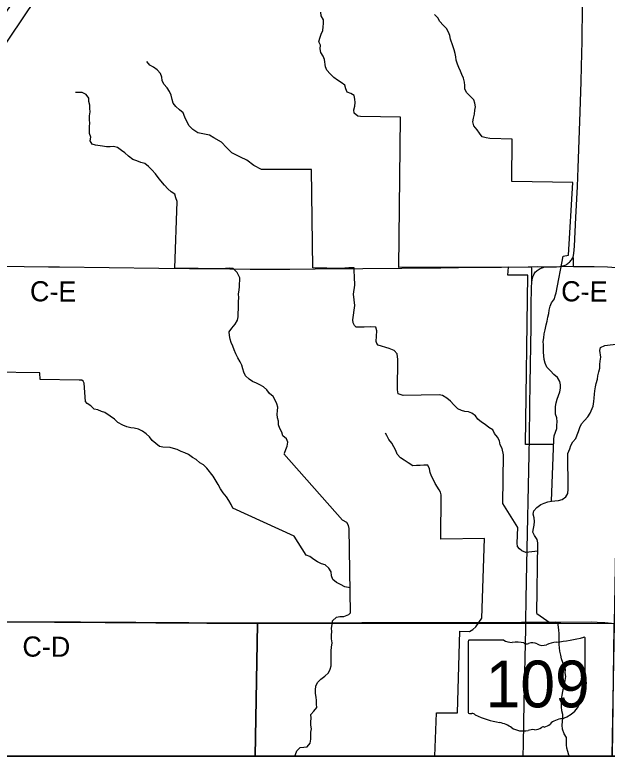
# Model space of a CAD drawing. Extents: x -21.7 to 34, y 0 to 22.
# Drawn here: x 25.914 to 27.584, y 14.078 to 16.19 of the extents above; entities that cross this region are included whole.
import ezdxf

# ---------------------------------------------------------------- set-up
doc = ezdxf.new("R2010")
doc.units = 0
for name, color, linetype in [('Default', 7, 'Continuous'), ('GM_X_County_Road', 7, 'Continuous'), ('GM_X_County_Road_Text', 7, 'Continuous'), ('GM_X_Interchange_Ramps', 7, 'Continuous'), ('GM_X_Minor_River', 7, 'Continuous'), ('GM_X_State_Location', 7, 'Continuous'), ('GM_X_State_Route', 7, 'Continuous'), ('GM_X_State_Shield', 7, 'Continuous'), ('GM_X_Township_Road', 7, 'Continuous'), ('SH_Data', 7, 'Continuous'), ('SH_Text', 7, 'Continuous')]:
    doc.layers.add(name, color=color, linetype=linetype)

msp = doc.modelspace()

# ---------------------------------------------------------------- linework, layer by layer
at = {"layer": 'Default'}
for points in [[(25.588, 14.1), (26.5915, 14.1), (26.5986, 14.4731), (25.5956, 14.4795)], [(26.5915, 14.1), (27.5993, 14.1), (27.6043, 14.466), (27.6038, 14.4739), (26.5986, 14.4731)]]:
    msp.add_lwpolyline(points, close=True, dxfattribs=at)
at = {"layer": 'GM_X_County_Road'}
for points in [[(27.4894, 15.481), (27.4896, 15.4845), (27.4893, 15.4993), (27.4893, 15.5015), (27.4892, 15.5035), (27.4892, 15.5045), (27.4888, 15.5064), (27.4882, 15.5073)], [(25.6145, 15.484), (25.6886, 15.4831), (25.7322, 15.4829), (25.785, 15.4821), (25.9404, 15.4804), (26.0088, 15.48), (26.0399, 15.4796), (26.3197, 15.4763), (26.4068, 15.4754), (26.4628, 15.4746), (26.5778, 15.4735), (26.6897, 15.4735), (26.7613, 15.474), (26.895, 15.4751), (27.1157, 15.4769), (27.1655, 15.4774), (27.2867, 15.4786), (27.3614, 15.4796), (27.3714, 15.4798)], [(27.4416, 15.48), (27.4508, 15.4806), (27.4543, 15.4811)], [(27.4543, 15.4811), (27.4623, 15.4811), (27.4894, 15.481)], [(27.4894, 15.481), (27.5228, 15.4808), (27.5477, 15.4805), (27.5851, 15.4792), (27.6231, 15.4773)], [(27.3714, 15.4798), (27.3893, 15.4802), (27.3987, 15.4799), (27.4084, 15.4794)], [(27.3717, 15.439), (27.3718, 15.4424), (27.372, 15.4475), (27.372, 15.4518), (27.3715, 15.4758), (27.3714, 15.4798)], [(27.4084, 15.4794), (27.4135, 15.4794), (27.4197, 15.4798), (27.4416, 15.48)], [(25.5958, 14.4815), (25.6644, 14.4811), (25.6954, 14.4811), (25.7576, 14.4806), (25.8197, 14.4801), (25.8788, 14.4799), (25.9627, 14.4791), (26.0311, 14.479), (26.0995, 14.4784), (26.1679, 14.4781), (26.255, 14.4775), (26.4042, 14.4765), (26.513, 14.476), (26.6187, 14.4755), (26.6965, 14.4758), (26.8923, 14.4765), (27.0291, 14.4769), (27.0913, 14.4771), (27.2374, 14.477), (27.3431, 14.4775), (27.3462, 14.4775), (27.355, 14.4777)], [(27.355, 14.4777), (27.4534, 14.4782), (27.5404, 14.4786), (27.556, 14.4782), (27.5778, 14.4767), (27.5963, 14.4748), (27.6052, 14.4738)]]:
    msp.add_lwpolyline(points, dxfattribs=at)
at = {"layer": 'GM_X_Interchange_Ramps'}
msp.add_lwpolyline([(23.5167, 14.1), (27.5987, 14.1), (27.605, 14.4744), (27.6229, 15.4779), (27.6372, 16.2146)], dxfattribs=at)
at = {"layer": 'GM_X_Minor_River'}
for points in [[(26.8888, 15.9039), (26.8816, 15.9048), (26.8712, 15.913), (26.8699, 15.9225), (26.8724, 15.9323), (26.8734, 15.9429), (26.8729, 15.9528), (26.8712, 15.9627), (26.8615, 15.9683), (26.8513, 15.9719), (26.8477, 15.9815), (26.8442, 15.9918), (26.8345, 15.9992), (26.824, 16.0059), (26.8136, 16.0137), (26.8032, 16.0235), (26.7936, 16.0339), (26.7896, 16.0435), (26.7871, 16.064), (26.7831, 16.0736), (26.7769, 16.0844), (26.7749, 16.0943), (26.7762, 16.1045), (26.7715, 16.1141), (26.7737, 16.1247), (26.7777, 16.1352), (26.7821, 16.1458), (26.7839, 16.1564), (26.7845, 16.1662), (26.784, 16.1757), (26.7778, 16.1869), (26.7773, 16.1975)], [(27.2535, 15.8418), (27.2436, 15.8432), (27.2323, 15.8465), (27.2246, 15.8561), (27.2176, 15.8658), (27.2084, 15.8774), (27.2056, 15.8881), (27.2078, 15.8986), (27.2099, 15.9104), (27.2113, 15.9213), (27.2131, 15.9312), (27.2114, 15.9411), (27.2086, 15.9506), (27.1989, 15.9599), (27.1886, 15.9704), (27.1827, 15.9804), (27.1826, 15.9907), (27.1821, 16.0002), (27.1789, 16.012), (27.1746, 16.0216), (27.1706, 16.0316), (27.1663, 16.0419), (27.162, 16.0515), (27.1588, 16.0622), (27.1572, 16.0717), (27.1559, 16.0812), (27.1531, 16.0919), (27.1491, 16.1023), (27.1428, 16.1214), (27.1403, 16.1317), (27.1372, 16.1416), (27.1317, 16.1512), (27.1217, 16.1609), (27.1128, 16.171), (27.1066, 16.1818), (27.097, 16.1915)], [(26.416, 15.867), (26.4059, 15.8771), (26.3979, 15.8909), (26.3929, 15.9021), (26.389, 15.9139), (26.3782, 15.9225), (26.3681, 15.9318), (26.3608, 15.9415), (26.358, 15.9514), (26.3552, 15.9636), (26.3501, 15.9736), (26.3439, 15.984), (26.3343, 15.9945), (26.3296, 16.0048), (26.3287, 16.0143), (26.3244, 16.025), (26.3151, 16.0347), (26.3051, 16.0422), (26.295, 16.0485), (26.2865, 16.0582), (26.2861, 16.0585)], [(26.3717, 15.6641), (26.3678, 15.6741), (26.365, 15.6848), (26.3549, 15.6915), (26.3453, 15.6997), (26.3356, 15.7101), (26.3253, 15.7217), (26.3183, 15.7314), (26.3106, 15.7418), (26.2998, 15.7527), (26.2906, 15.7628), (26.2805, 15.7713), (26.2692, 15.7739), (26.2576, 15.7783), (26.2467, 15.7827), (26.2343, 15.7913), (26.2243, 15.8011), (26.2146, 15.8077), (26.203, 15.816), (26.1925, 15.8185), (26.1826, 15.8179), (26.1727, 15.8181), (26.161, 15.8203), (26.1413, 15.8223), (26.1316, 15.8255), (26.1265, 15.8351), (26.1282, 15.845), (26.1247, 15.8553), (26.1241, 15.8648), (26.1247, 15.875), (26.1254, 15.8849), (26.1248, 15.8944), (26.1243, 15.9058), (26.1261, 15.9164), (26.1252, 15.9259), (26.1254, 15.9354), (26.123, 15.9457), (26.1228, 15.9555), (26.1151, 15.9656), (26.1042, 15.9711), (26.0853, 15.9716), (26.0849, 15.9708)], [(27.4333, 14.9788), (27.3539, 14.979), (27.3609, 15.456), (27.3044, 15.4565), (27.3057, 15.4785), (26.9964, 15.4775), (27.0014, 15.9017), (26.8888, 15.9039)], [(26.6098, 15.7541), (26.5881, 15.7656), (26.568, 15.7805), (26.5503, 15.7888), (26.5263, 15.8015), (26.5107, 15.8159), (26.4963, 15.8314), (26.4753, 15.8433), (26.463, 15.8511), (26.4304, 15.8578), (26.416, 15.867)], [(27.441, 15.4064), (27.4604, 15.5096), (27.4753, 15.5127), (27.4873, 15.717), (27.3151, 15.7205), (27.3164, 15.8393), (27.2535, 15.8418)], [(27.1102, 15.1189), (27.0092, 15.1169), (26.9953, 15.1218), (26.9933, 15.1332), (26.9938, 15.2183), (26.9922, 15.2339), (26.9837, 15.2435), (26.9698, 15.2495), (26.9389, 15.2586), (26.9349, 15.2632), (26.9327, 15.2694), (26.9346, 15.2993), (26.9322, 15.3092), (26.9178, 15.3103), (26.8995, 15.3096), (26.8764, 15.3093), (26.8716, 15.3144), (26.8683, 15.3217), (26.8674, 15.33), (26.8729, 15.3709), (26.8687, 15.4025), (26.8731, 15.4278), (26.8721, 15.451), (26.8706, 15.4681), (26.8708, 15.4769), (26.8557, 15.4768), (26.8336, 15.475), (26.7547, 15.4768), (26.7502, 15.7544), (26.6098, 15.7541)], [(26.5481, 15.4488), (26.5408, 15.4634), (26.5298, 15.4746), (26.5187, 15.476), (26.4974, 15.4742), (26.3647, 15.476), (26.3717, 15.6641)], [(26.1131, 15.0998), (26.1093, 15.1519), (26.107, 15.1577), (26.1027, 15.1604), (26.0955, 15.1601), (25.9855, 15.1618), (25.9844, 15.1808), (25.8494, 15.1827), (25.8553, 15.484), (25.0932, 15.4885)], [(26.6746, 14.9547), (26.6778, 14.9645), (26.6819, 14.9743), (26.684, 14.9853), (26.6797, 14.9949), (26.6696, 15.0034), (26.6665, 15.0138), (26.6614, 15.0237), (26.6578, 15.0345), (26.6573, 15.0443), (26.6545, 15.0543), (26.654, 15.0641), (26.6546, 15.074), (26.6556, 15.0842), (26.6524, 15.0938), (26.6481, 15.1041), (26.6426, 15.1141), (26.6322, 15.1227), (26.6245, 15.1324), (26.6148, 15.1413), (26.6051, 15.1472), (26.595, 15.1513), (26.5844, 15.156), (26.5744, 15.1627), (26.564, 15.1728), (26.56, 15.1824), (26.5572, 15.192), (26.5537, 15.2023), (26.5497, 15.2122), (26.5428, 15.223), (26.537, 15.2342), (26.5323, 15.2453), (26.5291, 15.2564), (26.524, 15.266), (26.5209, 15.2759), (26.5192, 15.2862), (26.5187, 15.2965), (26.5261, 15.3065), (26.5355, 15.3177), (26.5422, 15.329), (26.544, 15.3388), (26.5439, 15.3502), (26.5445, 15.36), (26.5443, 15.3695), (26.5446, 15.3817), (26.5456, 15.3923), (26.5451, 15.4033), (26.5461, 15.4139), (26.5475, 15.4241), (26.5481, 15.4488)], [(27.4339, 14.9932), (27.4353, 15.003), (27.4382, 15.0136), (27.4422, 15.0234), (27.442, 15.0329), (27.4434, 15.0431), (27.4425, 15.0537), (27.439, 15.0644), (27.4388, 15.0743), (27.4387, 15.0857), (27.4405, 15.0959), (27.4434, 15.1061), (27.4474, 15.1166), (27.4511, 15.1276), (27.4525, 15.1378), (27.4527, 15.1473), (27.451, 15.1568), (27.4441, 15.1672), (27.434, 15.1765), (27.4248, 15.1866), (27.414, 15.1971), (27.4094, 15.2082), (27.4066, 15.2185), (27.4053, 15.2284), (27.4052, 15.2394), (27.405, 15.2497), (27.4045, 15.26), (27.4043, 15.2694), (27.4053, 15.2797), (27.4071, 15.291), (27.4093, 15.3024), (27.4123, 15.316), (27.4148, 15.3265), (27.417, 15.3379), (27.4195, 15.3477), (27.4208, 15.3575), (27.4234, 15.3685), (27.4274, 15.3786), (27.4356, 15.3899), (27.4379, 15.3976), (27.441, 15.4064)], [(27.4739, 14.9536), (27.4788, 14.9664), (27.4821, 14.9762), (27.4876, 14.9863), (27.4962, 14.996), (27.4998, 15.0058), (27.5031, 15.0156), (27.5072, 15.0269), (27.5116, 15.0366), (27.5209, 15.0467), (27.5295, 15.0564), (27.5365, 15.0668), (27.5446, 15.0871), (27.5464, 15.0996), (27.5478, 15.1095), (27.5484, 15.1205), (27.5494, 15.1303), (27.5516, 15.1409), (27.5533, 15.1511), (27.557, 15.1628), (27.5576, 15.1726), (27.5605, 15.184), (27.5634, 15.1941), (27.5633, 15.204), (27.5647, 15.2139), (27.5661, 15.2252), (27.564, 15.2436), (27.566, 15.2522), (27.578, 15.2576)], [(27.578, 15.2576), (27.6168, 15.2625)], [(27.2917, 14.9497), (27.288, 14.9672), (27.2829, 14.978), (27.2805, 14.9887), (27.2754, 14.999), (27.2662, 15.0102), (27.2615, 15.0198), (27.251, 15.0265), (27.2399, 15.0347), (27.2298, 15.0418), (27.2197, 15.0504), (27.2128, 15.06), (27.2031, 15.0671), (27.1929, 15.0711), (27.1831, 15.0721), (27.1733, 15.0749), (27.1635, 15.0796), (27.1524, 15.091), (27.1428, 15.1007), (27.1319, 15.1096), (27.1204, 15.1172), (27.1102, 15.1189)], [(26.529, 14.7989), (26.5243, 14.8097), (26.5178, 14.8208), (26.5112, 14.8312), (26.5016, 14.8421), (26.4935, 14.8536), (26.4877, 14.8655), (26.4786, 14.8802), (26.4735, 14.8898), (26.4558, 14.9122), (26.4461, 14.9211), (26.436, 14.9274), (26.4252, 14.936), (26.4151, 14.9423), (26.4036, 14.9506), (26.3931, 14.9557), (26.3833, 14.959), (26.3716, 14.9645), (26.3618, 14.967), (26.3521, 14.9707), (26.3312, 14.9711), (26.3214, 14.9733), (26.3113, 14.9811), (26.3009, 14.99), (26.2936, 15.0001), (26.2839, 15.0086), (26.2735, 15.0165), (26.2622, 15.0224), (26.2505, 15.0246), (26.2407, 15.0259), (26.2293, 15.0281), (26.2188, 15.0329), (26.2042, 15.0404), (26.1946, 15.0501), (26.1826, 15.0584), (26.1681, 15.0689), (26.1583, 15.0714), (26.1478, 15.0766), (26.138, 15.0787), (26.1283, 15.0877), (26.1178, 15.094), (26.1131, 15.0998)], [(27.099, 14.869), (27.0947, 14.8793), (27.0885, 14.8897), (27.0853, 14.9), (27.0833, 14.9099), (27.0786, 14.9203), (27.0676, 14.9209), (27.0569, 14.9196), (27.0471, 14.9191), (27.0364, 14.9186), (27.0233, 14.9268), (27.0121, 14.9347), (27.0017, 14.9414), (26.9924, 14.9518), (26.9881, 14.9622), (26.9827, 14.9722), (26.9772, 14.9825), (26.9687, 14.9926), (26.9633, 15.0037), (26.9597, 15.0106)], [(27.4271, 14.8191), (27.4339, 14.9932)], [(27.4746, 14.8526), (27.4739, 14.9536)], [(26.8566, 14.7423), (26.8549, 14.7507), (26.8502, 14.7584), (26.8382, 14.7658), (26.6722, 14.9521)], [(27.3884, 14.6776), (27.3551, 14.6742), (27.3438, 14.6786), (27.3375, 14.6845), (27.3319, 14.691), (27.3303, 14.7006), (27.3324, 14.7449), (27.2904, 14.8123), (27.2917, 14.9497)], [(27.0987, 14.1), (27.1031, 14.222), (27.1619, 14.2226), (27.1685, 14.4525), (27.1965, 14.4519), (27.2054, 14.4574), (27.2143, 14.4651), (27.2308, 14.4891), (27.238, 14.7136), (27.115, 14.7114), (27.116, 14.8364), (27.114, 14.8443), (27.1104, 14.851), (27.099, 14.869)], [(27.3887, 14.7012), (27.3867, 14.7111), (27.3797, 14.7222), (27.375, 14.7318), (27.3764, 14.7417), (27.3785, 14.7515), (27.3791, 14.7613), (27.3786, 14.7716), (27.3754, 14.7819), (27.3772, 14.7918), (27.3858, 14.8014), (27.3973, 14.8095), (27.4069, 14.8135), (27.4172, 14.8171), (27.4271, 14.8191), (27.4367, 14.82), (27.4473, 14.8206), (27.4572, 14.8234), (27.4676, 14.8311), (27.4732, 14.8409), (27.4746, 14.8526)], [(26.7357, 14.6668), (26.7017, 14.7199), (26.529, 14.7989)], [(26.8609, 14.5042), (26.8566, 14.7423)], [(27.3859, 14.5023), (27.3887, 14.7012)], [(26.8596, 14.5745), (26.8444, 14.5774), (26.832, 14.5838), (26.8215, 14.5897), (26.8111, 14.5979), (26.8068, 14.6086), (26.8059, 14.6193), (26.7997, 14.6297), (26.7893, 14.639), (26.7791, 14.6427), (26.7679, 14.6475), (26.757, 14.6542), (26.7459, 14.6631), (26.7357, 14.6668)], [(26.704, 14.1), (26.705, 14.1049), (26.709, 14.1147), (26.7188, 14.1243), (26.7286, 14.1252), (26.7382, 14.1265), (26.7471, 14.137), (26.7485, 14.148), (26.7484, 14.1574), (26.7486, 14.1673), (26.7504, 14.1775), (26.7491, 14.187), (26.7489, 14.1965), (26.7495, 14.2068), (26.7486, 14.217), (26.7568, 14.2271), (26.7658, 14.2368), (26.7649, 14.247), (26.7647, 14.2565), (26.7635, 14.2668), (26.7614, 14.2771), (26.7617, 14.2874), (26.7623, 14.2976), (26.7671, 14.3074), (26.7772, 14.3174), (26.788, 14.3255), (26.7985, 14.3347), (26.8029, 14.3449), (26.8061, 14.3547), (26.806, 14.3661), (26.8062, 14.3756), (26.8058, 14.387), (26.806, 14.3968), (26.807, 14.4074), (26.8084, 14.4192), (26.8072, 14.4306), (26.8074, 14.4408), (26.808, 14.4511), (26.8067, 14.461), (26.8085, 14.4712), (26.8095, 14.4818), (26.8211, 14.4918), (26.8306, 14.4935), (26.8413, 14.4936), (26.8556, 14.4992), (26.8609, 14.5042)], [(27.3859, 14.5023), (27.4236, 14.476), (27.4388, 14.478)], [(27.4777, 14.1), (27.4759, 14.1032), (27.4735, 14.1128), (27.4703, 14.1223), (27.4698, 14.1318), (27.4693, 14.1432), (27.4695, 14.1527), (27.4633, 14.1631), (27.4587, 14.1761), (27.4578, 14.1875), (27.4584, 14.1974), (27.4594, 14.2072), (27.4589, 14.2179), (27.4561, 14.2274), (27.4556, 14.2388), (27.4555, 14.2498), (27.4557, 14.2605), (27.4579, 14.2722), (27.4593, 14.282), (27.4614, 14.2918), (27.4636, 14.3032), (27.4657, 14.3138), (27.4675, 14.3243), (27.4662, 14.3346), (27.4668, 14.3445), (27.464, 14.354), (27.4589, 14.3644), (27.4554, 14.3743), (27.4533, 14.385), (27.4506, 14.3957), (27.4504, 14.4052), (27.4487, 14.4147), (27.4486, 14.4257), (27.4489, 14.4364), (27.4487, 14.4459), (27.4482, 14.4557), (27.4458, 14.4709), (27.4429, 14.4767), (27.4388, 14.478)]]:
    msp.add_lwpolyline(points, dxfattribs=at)
at = {"layer": 'GM_X_State_Route'}
for points in [[(27.4543, 15.4811), (27.4568, 15.4815), (27.4598, 15.4823), (27.4627, 15.4832), (27.4655, 15.4843), (27.4683, 15.4856), (27.4709, 15.4871), (27.4735, 15.4888), (27.4758, 15.4907), (27.4781, 15.4927), (27.4802, 15.4949), (27.482, 15.4973), (27.4837, 15.4998), (27.4855, 15.5024), (27.4874, 15.5053), (27.4882, 15.5073), (27.4904, 15.5174), (27.4918, 15.5384), (27.4961, 15.6191), (27.5008, 15.7061), (27.5029, 15.7589), (27.5072, 15.8894), (27.5108, 16.0013), (27.5122, 16.0448), (27.514, 16.1162), (27.5148, 16.2155)], [(27.4416, 15.48), (27.4508, 15.4806), (27.4543, 15.4811)], [(27.3476, 14.1), (27.3483, 14.1335), (27.3504, 14.2516), (27.3546, 14.4599), (27.355, 14.4777), (27.3564, 14.5438), (27.3582, 14.6402), (27.3643, 14.951), (27.3651, 14.9976), (27.3666, 15.0877), (27.3673, 15.1499), (27.3697, 15.3116), (27.3703, 15.3707), (27.3712, 15.4214), (27.3717, 15.436), (27.3717, 15.439), (27.3725, 15.4423), (27.3738, 15.4485), (27.3747, 15.4515), (27.3773, 15.4573), (27.3789, 15.4601), (27.3806, 15.4627), (27.3826, 15.4652), (27.3848, 15.4675), (27.3872, 15.4696), (27.3897, 15.4715), (27.3924, 15.4732), (27.3952, 15.4747), (27.3981, 15.476), (27.4011, 15.4771), (27.4084, 15.4794)], [(27.4084, 15.4794), (27.4135, 15.4794), (27.4197, 15.4798), (27.4416, 15.48)]]:
    msp.add_lwpolyline(points, dxfattribs=at)
at = {"layer": 'GM_X_State_Shield'}
for p, q in [((27.2926, 14.4271), (27.196, 14.4271)), ((27.5224, 14.3273), (27.5224, 14.432)), ((27.1928, 14.4236), (27.1928, 14.2235)), ((27.5224, 14.3274), (27.5224, 14.3273))]:
    msp.add_line(p, q, dxfattribs=at)
for centre, major_axis, start_param, end_param in [((27.1966, 14.4241), (0.00382, 0), 1.712693, 3.28349), ((27.3156, 14.4503), (0.037, 0), 4.042523, 4.731795), ((27.405, 14.6999), (0.3495, 0), 4.814394, 5.042369), ((27.5187, 14.4325), (0.00367, 0), 6.141152, 7.989035), ((27.3278, 14.3147), (0.133, 0), 1.404758, 1.657858), ((27.358, 14.4251), (0.0107, 0), 3.836095, 5.185415), ((27.3737, 14.402), (0.0222, 0), 0.950623, 2.079405), ((27.4024, 14.4337), (0.0267, 0), 4.081561, 5.145723), ((27.4496, 14.3659), (0.0703, 0), 1.699011, 2.107814), ((27.5215, 14.3197), (0.00568, 0), 1.883978, 3.671073), ((27.5185, 14.3269), (0.00393, 0), 5.05454, 6.418171), ((27.4854, 14.3064), (0.0341, 0), 5.934695, 6.695948), ((27.4246, 14.2702), (0.0874, 0), 5.101752, 6.440018), ((27.5355, 14.2835), (0.0248, 0), 2.387724, 3.262537), ((27.1966, 14.2231), (0.00385, 0), 3.00124, 4.508301), ((27.1972, 14.2435), (0.0294, 0), 4.665946, 4.897461), ((27.2032, 14.212), (0.0106, 0), 0.519207, 1.627899), ((27.337, 14.3918), (0.2524, 0), 4.195997, 4.488961), ((27.2618, 14.1336), (0.079, 0), 0.823519, 1.323587), ((27.4614, 14.1673), (0.0479, 0), 1.647645, 2.488434), ((27.3472, 14.211), (0.0501, 0), 4.026481, 4.996735), ((27.3762, 14.1418), (0.0412, 0), 1.495662, 1.94098), ((27.3798, 14.196), (0.0267, 0), 4.691044, 5.507374), ((27.404, 14.1766), (0.00752, 0), 1.147584, 2.315152), ((27.4008, 14.2041), (0.0282, 0), 4.937069, 5.64225)]:
    msp.add_ellipse(centre, major_axis=major_axis, ratio=0.8, start_param=start_param, end_param=end_param, dxfattribs=at)
at = {"layer": 'GM_X_Township_Road'}
for points in [[(25.6145, 15.484), (25.6886, 15.4831), (25.7322, 15.4829), (25.785, 15.4821), (25.9404, 15.4804), (26.0088, 15.48), (26.0399, 15.4796), (26.3197, 15.4763), (26.4068, 15.4754), (26.4628, 15.4746), (26.5778, 15.4735), (26.6897, 15.4735), (26.7613, 15.474), (26.895, 15.4751), (27.1157, 15.4769), (27.1655, 15.4774), (27.2867, 15.4786), (27.3614, 15.4796), (27.3714, 15.4798)], [(27.4416, 15.48), (27.4508, 15.4806), (27.4543, 15.4811)], [(27.4543, 15.4811), (27.4623, 15.4811), (27.4894, 15.481)], [(27.4894, 15.481), (27.5228, 15.4808), (27.5477, 15.4805), (27.5851, 15.4792), (27.6231, 15.4773)], [(27.3714, 15.4798), (27.3893, 15.4802), (27.3987, 15.4799), (27.4084, 15.4794)], [(27.4084, 15.4794), (27.4135, 15.4794), (27.4197, 15.4798), (27.4416, 15.48)]]:
    msp.add_lwpolyline(points, dxfattribs=at)
at = {"layer": 'SH_Data'}
msp.add_line((23.5167, 14.1), (30.3167, 14.1), dxfattribs=at)
msp.add_lwpolyline([(23.5167, 20.9), (30.3167, 20.9), (30.3167, 14.1), (23.5167, 14.1)], close=True, dxfattribs=at)
at = {"layer": 'SH_Text'}
msp.add_lwpolyline([(23.5845, 12.6836), (26.8092, 17.4787), (23.5845, 12.9954)], close=True, dxfattribs=at)

# ---------------------------------------------------------------- texts
at = {"layer": 'GM_X_County_Road_Text'}
for s, rotation, p in [('C-E', 359.5714, (25.9564, 15.3825)), ('C-E', 359.577, (27.4545, 15.3825)), ('C-D', 359.5871, (25.935, 14.3809))]:
    msp.add_text(s, height=0.05682, rotation=rotation, dxfattribs=at).set_placement(p)
at = {"layer": 'GM_X_State_Location'}
for s in ['s', 'r']:
    msp.add_text(s, height=0.000189, dxfattribs=at).set_placement((27.3539, 14.3103))
msp.add_text('109', height=0.000189, rotation=0, dxfattribs=at).set_placement((27.287, 14.2965))
at = {"layer": 'GM_X_State_Shield'}
msp.add_text('109', height=0.13184, dxfattribs=at).set_placement((27.2413, 14.2376))

doc.saveas('drawing.dxf')
